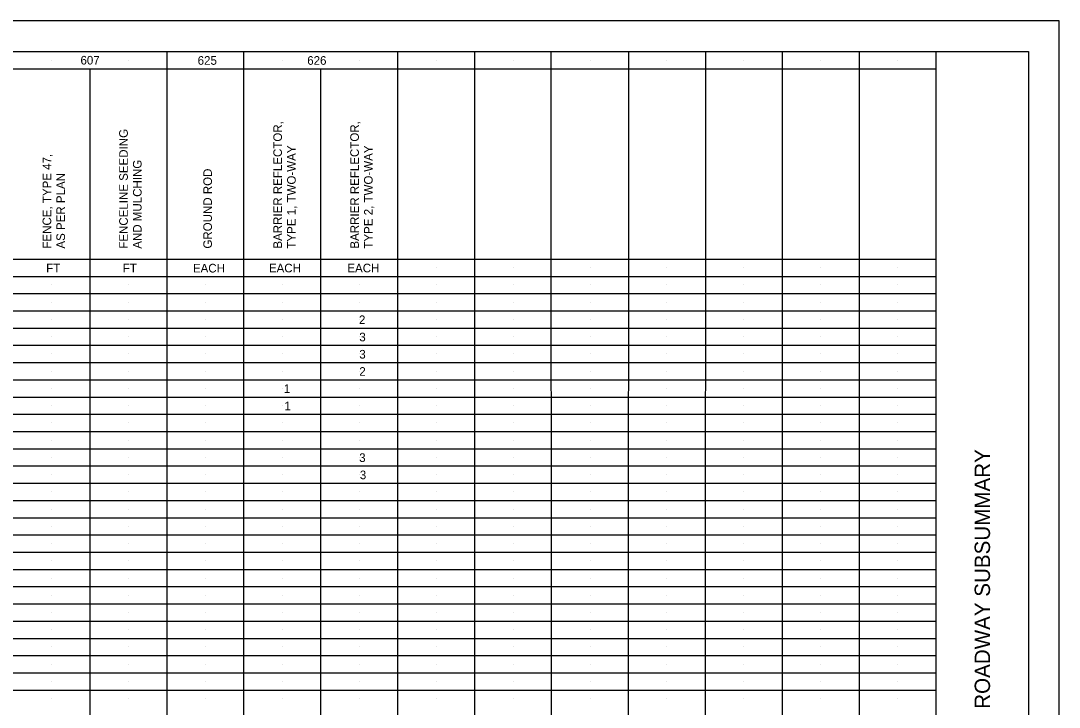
# Model space of a CAD drawing. Extents: x 2073163.9 to 2073197.9, y 634076.5 to 634098.5.
# Drawn here: x 2073181.07 to 2073197.95, y 634087.4 to 634098.55 of the extents above; entities that cross this region are included whole.
import ezdxf

# ---------------------------------------------------------------- set-up
doc = ezdxf.new("R2010")
doc.units = 0
for name, color, linetype in [('SH_Border', 7, 'Continuous'), ('SH_Cut_Line', 7, 'Continuous'), ('SH_Data', 7, 'Continuous'), ('SH_Text', 7, 'Continuous')]:
    doc.layers.add(name, color=color, linetype=linetype)

msp = doc.modelspace()

# ---------------------------------------------------------------- linework, layer by layer
at = {"layer": 'SH_Border'}
msp.add_line((2073195.946, 634077.05), (2073195.946, 634098.05), dxfattribs=at)
msp.add_lwpolyline([(2073165.446, 634098.05), (2073197.446, 634098.05), (2073197.446, 634077.05), (2073165.446, 634077.05)], close=True, dxfattribs=at)
at = {"layer": 'SH_Cut_Line'}
msp.add_lwpolyline([(2073163.946, 634076.55), (2073197.946, 634076.55), (2073197.946, 634098.55), (2073163.946, 634098.55)], close=True, dxfattribs=at)
at = {"layer": 'SH_Data'}
for p, q in [((2073183.446, 634077.05), (2073183.447, 634098.05)), ((2073184.696, 634077.05), (2073184.696, 634098.05)), ((2073187.196, 634077.05), (2073187.196, 634098.05)), ((2073188.446, 634077.05), (2073188.446, 634098.05)), ((2073189.696, 634077.05), (2073189.69, 634098.048)), ((2073190.946, 634077.05), (2073190.95, 634098.05)), ((2073192.196, 634077.05), (2073192.2, 634098.05)), ((2073193.446, 634077.05), (2073193.45, 634098.05)), ((2073194.696, 634077.047), (2073194.7, 634098.047)), ((2073181.571, 634097.91), (2073181.571, 634097.91)), ((2073181.571, 634097.91), (2073181.571, 634097.91)), ((2073182.821, 634097.91), (2073182.821, 634097.91)), ((2073182.821, 634097.91), (2073182.821, 634097.91)), ((2073182.821, 634097.91), (2073182.821, 634097.91)), ((2073184.071, 634097.91), (2073184.071, 634097.91)), ((2073184.071, 634097.91), (2073184.071, 634097.91)), ((2073184.071, 634097.91), (2073184.071, 634097.91)), ((2073184.071, 634097.91), (2073184.071, 634097.91)), ((2073185.321, 634097.91), (2073185.321, 634097.91)), ((2073185.321, 634097.91), (2073185.321, 634097.91)), ((2073185.321, 634097.91), (2073185.321, 634097.91)), ((2073185.321, 634097.91), (2073185.321, 634097.91)), ((2073185.321, 634097.91), (2073185.321, 634097.91)), ((2073186.571, 634097.91), (2073186.571, 634097.91)), ((2073187.821, 634097.91), (2073187.821, 634097.91)), ((2073189.071, 634097.91), (2073189.071, 634097.91)), ((2073190.321, 634097.91), (2073190.321, 634097.91)), ((2073191.571, 634097.91), (2073191.571, 634097.91)), ((2073192.821, 634097.91), (2073192.821, 634097.91)), ((2073194.071, 634097.91), (2073194.071, 634097.91)), ((2073195.321, 634097.91), (2073195.321, 634097.91)), ((2073172.201, 634097.77), (2073195.946, 634097.77)), ((2073182.196, 634077.05), (2073182.196, 634097.77)), ((2073185.946, 634077.05), (2073185.946, 634097.77)), ((2073172.201, 634094.678), (2073195.946, 634094.678)), ((2073181.571, 634094.538), (2073181.571, 634094.538)), ((2073181.571, 634094.538), (2073181.571, 634094.538)), ((2073182.821, 634094.538), (2073182.821, 634094.538)), ((2073182.821, 634094.538), (2073182.821, 634094.538)), ((2073182.821, 634094.538), (2073182.821, 634094.538)), ((2073184.071, 634094.538), (2073184.071, 634094.538)), ((2073184.071, 634094.538), (2073184.071, 634094.538)), ((2073184.071, 634094.538), (2073184.071, 634094.538)), ((2073184.071, 634094.538), (2073184.071, 634094.538)), ((2073185.321, 634094.538), (2073185.321, 634094.538)), ((2073185.321, 634094.538), (2073185.321, 634094.538)), ((2073185.321, 634094.538), (2073185.321, 634094.538)), ((2073185.321, 634094.538), (2073185.321, 634094.538)), ((2073185.321, 634094.538), (2073185.321, 634094.538)), ((2073186.571, 634094.538), (2073186.571, 634094.538)), ((2073187.821, 634094.538), (2073187.821, 634094.538)), ((2073189.071, 634094.538), (2073189.071, 634094.538)), ((2073190.321, 634094.538), (2073190.321, 634094.538)), ((2073191.571, 634094.538), (2073191.571, 634094.538)), ((2073192.821, 634094.538), (2073192.821, 634094.538)), ((2073194.071, 634094.538), (2073194.071, 634094.538)), ((2073195.321, 634094.538), (2073195.321, 634094.538)), ((2073165.446, 634094.398), (2073195.946, 634094.398)), ((2073181.571, 634094.258), (2073181.571, 634094.258)), ((2073182.821, 634094.258), (2073182.821, 634094.258)), ((2073184.071, 634094.258), (2073184.071, 634094.258)), ((2073185.321, 634094.258), (2073185.321, 634094.258)), ((2073186.571, 634094.258), (2073186.571, 634094.258)), ((2073187.821, 634094.258), (2073187.821, 634094.258)), ((2073189.071, 634094.258), (2073189.071, 634094.258)), ((2073190.321, 634094.258), (2073190.321, 634094.258)), ((2073191.571, 634094.258), (2073191.571, 634094.258)), ((2073192.821, 634094.258), (2073192.821, 634094.258)), ((2073194.071, 634094.258), (2073194.071, 634094.258)), ((2073195.321, 634094.258), (2073195.321, 634094.258)), ((2073165.44, 634094.118), (2073195.948, 634094.118)), ((2073181.571, 634093.978), (2073181.571, 634093.978)), ((2073182.821, 634093.978), (2073182.821, 634093.978)), ((2073184.071, 634093.978), (2073184.071, 634093.978)), ((2073185.321, 634093.978), (2073185.321, 634093.978)), ((2073186.571, 634093.978), (2073186.571, 634093.978)), ((2073187.821, 634093.978), (2073187.821, 634093.978)), ((2073189.071, 634093.978), (2073189.071, 634093.978)), ((2073190.321, 634093.978), (2073190.321, 634093.978)), ((2073191.571, 634093.978), (2073191.571, 634093.978)), ((2073192.821, 634093.978), (2073192.821, 634093.978)), ((2073194.071, 634093.978), (2073194.071, 634093.978)), ((2073195.321, 634093.978), (2073195.321, 634093.978)), ((2073165.45, 634093.838), (2073195.947, 634093.838)), ((2073181.571, 634093.698), (2073181.571, 634093.698)), ((2073182.821, 634093.698), (2073182.821, 634093.698)), ((2073184.071, 634093.698), (2073184.071, 634093.698)), ((2073185.321, 634093.698), (2073185.321, 634093.698)), ((2073186.571, 634093.698), (2073186.571, 634093.698)), ((2073187.821, 634093.698), (2073187.821, 634093.698)), ((2073189.071, 634093.698), (2073189.071, 634093.698)), ((2073190.321, 634093.698), (2073190.321, 634093.698)), ((2073191.571, 634093.698), (2073191.571, 634093.698)), ((2073192.821, 634093.698), (2073192.821, 634093.698)), ((2073194.071, 634093.698), (2073194.071, 634093.698)), ((2073195.321, 634093.698), (2073195.321, 634093.698)), ((2073165.45, 634093.558), (2073195.947, 634093.558)), ((2073181.571, 634093.418), (2073181.571, 634093.418)), ((2073182.821, 634093.418), (2073182.821, 634093.418)), ((2073184.071, 634093.418), (2073184.071, 634093.418)), ((2073185.321, 634093.418), (2073185.321, 634093.418)), ((2073186.571, 634093.418), (2073186.571, 634093.418)), ((2073187.821, 634093.418), (2073187.821, 634093.418)), ((2073189.071, 634093.418), (2073189.071, 634093.418)), ((2073190.321, 634093.418), (2073190.321, 634093.418)), ((2073191.571, 634093.418), (2073191.571, 634093.418)), ((2073192.821, 634093.418), (2073192.821, 634093.418)), ((2073194.071, 634093.418), (2073194.071, 634093.418)), ((2073195.321, 634093.418), (2073195.321, 634093.418)), ((2073165.447, 634093.278), (2073195.949, 634093.278)), ((2073181.571, 634093.138), (2073181.571, 634093.138)), ((2073182.821, 634093.138), (2073182.821, 634093.138)), ((2073184.071, 634093.138), (2073184.071, 634093.138)), ((2073185.321, 634093.138), (2073185.321, 634093.138)), ((2073186.571, 634093.138), (2073186.571, 634093.138)), ((2073187.821, 634093.138), (2073187.821, 634093.138)), ((2073189.071, 634093.138), (2073189.071, 634093.138)), ((2073190.321, 634093.138), (2073190.321, 634093.138)), ((2073191.571, 634093.138), (2073191.571, 634093.138)), ((2073192.821, 634093.138), (2073192.821, 634093.138)), ((2073194.071, 634093.138), (2073194.071, 634093.138)), ((2073195.321, 634093.138), (2073195.321, 634093.138)), ((2073165.444, 634092.998), (2073195.947, 634092.998)), ((2073181.571, 634092.858), (2073181.571, 634092.858)), ((2073182.821, 634092.858), (2073182.821, 634092.858)), ((2073184.071, 634092.858), (2073184.071, 634092.858)), ((2073185.321, 634092.858), (2073185.321, 634092.858)), ((2073186.571, 634092.858), (2073186.571, 634092.858)), ((2073187.821, 634092.858), (2073187.821, 634092.858)), ((2073189.071, 634092.858), (2073189.071, 634092.858)), ((2073190.321, 634092.858), (2073190.321, 634092.858)), ((2073191.571, 634092.858), (2073191.571, 634092.858)), ((2073192.821, 634092.858), (2073192.821, 634092.858)), ((2073194.071, 634092.858), (2073194.071, 634092.858)), ((2073195.321, 634092.858), (2073195.321, 634092.858)), ((2073165.454, 634092.718), (2073195.947, 634092.718)), ((2073181.571, 634092.578), (2073181.571, 634092.578)), ((2073182.821, 634092.578), (2073182.821, 634092.578)), ((2073184.071, 634092.578), (2073184.071, 634092.578)), ((2073185.321, 634092.578), (2073185.321, 634092.578)), ((2073186.571, 634092.578), (2073186.571, 634092.578)), ((2073187.821, 634092.578), (2073187.821, 634092.578)), ((2073189.071, 634092.578), (2073189.071, 634092.578)), ((2073190.321, 634092.578), (2073190.321, 634092.578)), ((2073191.571, 634092.578), (2073191.571, 634092.578)), ((2073192.821, 634092.578), (2073192.821, 634092.578)), ((2073194.071, 634092.578), (2073194.071, 634092.578)), ((2073195.321, 634092.578), (2073195.321, 634092.578)), ((2073165.45, 634092.438), (2073195.943, 634092.438)), ((2073181.571, 634092.298), (2073181.571, 634092.298)), ((2073182.821, 634092.298), (2073182.821, 634092.298)), ((2073184.071, 634092.298), (2073184.071, 634092.298)), ((2073185.321, 634092.298), (2073185.321, 634092.298)), ((2073186.571, 634092.298), (2073186.571, 634092.298)), ((2073187.821, 634092.298), (2073187.821, 634092.298)), ((2073189.071, 634092.298), (2073189.071, 634092.298)), ((2073190.321, 634092.298), (2073190.321, 634092.298)), ((2073191.571, 634092.298), (2073191.571, 634092.298)), ((2073192.821, 634092.298), (2073192.821, 634092.298)), ((2073194.071, 634092.298), (2073194.071, 634092.298)), ((2073195.321, 634092.298), (2073195.321, 634092.298)), ((2073165.448, 634092.158), (2073195.943, 634092.158)), ((2073181.571, 634092.018), (2073181.571, 634092.018)), ((2073182.821, 634092.018), (2073182.821, 634092.018)), ((2073184.071, 634092.018), (2073184.071, 634092.018)), ((2073185.321, 634092.018), (2073185.321, 634092.018)), ((2073186.571, 634092.018), (2073186.571, 634092.018)), ((2073187.821, 634092.018), (2073187.821, 634092.018)), ((2073189.071, 634092.018), (2073189.071, 634092.018)), ((2073190.321, 634092.018), (2073190.321, 634092.018)), ((2073191.571, 634092.018), (2073191.571, 634092.018)), ((2073192.821, 634092.018), (2073192.821, 634092.018)), ((2073194.071, 634092.018), (2073194.071, 634092.018)), ((2073195.321, 634092.018), (2073195.321, 634092.018)), ((2073165.448, 634091.878), (2073195.943, 634091.878)), ((2073181.571, 634091.738), (2073181.571, 634091.738)), ((2073182.821, 634091.738), (2073182.821, 634091.738)), ((2073184.071, 634091.738), (2073184.071, 634091.738)), ((2073185.321, 634091.738), (2073185.321, 634091.738)), ((2073186.571, 634091.738), (2073186.571, 634091.738)), ((2073187.821, 634091.738), (2073187.821, 634091.738)), ((2073189.071, 634091.738), (2073189.071, 634091.738)), ((2073190.321, 634091.738), (2073190.321, 634091.738)), ((2073191.571, 634091.738), (2073191.571, 634091.738)), ((2073192.821, 634091.738), (2073192.821, 634091.738)), ((2073194.071, 634091.738), (2073194.071, 634091.738)), ((2073195.321, 634091.738), (2073195.321, 634091.738)), ((2073165.448, 634091.598), (2073195.948, 634091.598)), ((2073181.571, 634091.458), (2073181.571, 634091.458)), ((2073182.821, 634091.458), (2073182.821, 634091.458)), ((2073184.071, 634091.458), (2073184.071, 634091.458)), ((2073185.321, 634091.458), (2073185.321, 634091.458)), ((2073186.571, 634091.458), (2073186.571, 634091.458)), ((2073187.821, 634091.458), (2073187.821, 634091.458)), ((2073189.071, 634091.458), (2073189.071, 634091.458)), ((2073190.321, 634091.458), (2073190.321, 634091.458)), ((2073191.571, 634091.458), (2073191.571, 634091.458)), ((2073192.821, 634091.458), (2073192.821, 634091.458)), ((2073194.071, 634091.458), (2073194.071, 634091.458)), ((2073195.321, 634091.458), (2073195.321, 634091.458)), ((2073165.451, 634091.318), (2073195.939, 634091.318)), ((2073165.451, 634091.318), (2073195.944, 634091.318)), ((2073181.571, 634091.178), (2073181.571, 634091.178)), ((2073182.821, 634091.178), (2073182.821, 634091.178)), ((2073184.071, 634091.178), (2073184.071, 634091.178)), ((2073185.321, 634091.178), (2073185.321, 634091.178)), ((2073186.571, 634091.178), (2073186.571, 634091.178)), ((2073187.821, 634091.178), (2073187.821, 634091.178)), ((2073189.071, 634091.178), (2073189.071, 634091.178)), ((2073190.321, 634091.178), (2073190.321, 634091.178)), ((2073191.571, 634091.178), (2073191.571, 634091.178)), ((2073192.821, 634091.178), (2073192.821, 634091.178)), ((2073194.071, 634091.178), (2073194.071, 634091.178)), ((2073195.321, 634091.178), (2073195.321, 634091.178)), ((2073165.448, 634091.038), (2073195.944, 634091.038)), ((2073181.571, 634090.898), (2073181.571, 634090.898)), ((2073182.821, 634090.898), (2073182.821, 634090.898)), ((2073184.071, 634090.898), (2073184.071, 634090.898)), ((2073185.321, 634090.898), (2073185.321, 634090.898)), ((2073186.571, 634090.898), (2073186.571, 634090.898)), ((2073187.821, 634090.898), (2073187.821, 634090.898)), ((2073189.071, 634090.898), (2073189.071, 634090.898)), ((2073190.321, 634090.898), (2073190.321, 634090.898)), ((2073191.571, 634090.898), (2073191.571, 634090.898)), ((2073192.821, 634090.898), (2073192.821, 634090.898)), ((2073194.071, 634090.898), (2073194.071, 634090.898)), ((2073195.321, 634090.898), (2073195.321, 634090.898)), ((2073165.445, 634090.758), (2073195.942, 634090.758)), ((2073181.571, 634090.618), (2073181.571, 634090.618)), ((2073182.821, 634090.618), (2073182.821, 634090.618)), ((2073184.071, 634090.618), (2073184.071, 634090.618)), ((2073185.321, 634090.618), (2073185.321, 634090.618)), ((2073186.571, 634090.618), (2073186.571, 634090.618)), ((2073187.821, 634090.618), (2073187.821, 634090.618)), ((2073189.071, 634090.618), (2073189.071, 634090.618)), ((2073190.321, 634090.618), (2073190.321, 634090.618)), ((2073191.571, 634090.618), (2073191.571, 634090.618)), ((2073192.821, 634090.618), (2073192.821, 634090.618)), ((2073194.071, 634090.618), (2073194.071, 634090.618)), ((2073195.321, 634090.618), (2073195.321, 634090.618)), ((2073165.442, 634090.478), (2073195.946, 634090.478)), ((2073181.571, 634090.338), (2073181.571, 634090.338)), ((2073182.821, 634090.338), (2073182.821, 634090.338)), ((2073184.071, 634090.338), (2073184.071, 634090.338)), ((2073185.321, 634090.338), (2073185.321, 634090.338)), ((2073186.571, 634090.338), (2073186.571, 634090.338)), ((2073187.821, 634090.338), (2073187.821, 634090.338)), ((2073189.071, 634090.338), (2073189.071, 634090.338)), ((2073190.321, 634090.338), (2073190.321, 634090.338)), ((2073191.571, 634090.338), (2073191.571, 634090.338)), ((2073192.821, 634090.338), (2073192.821, 634090.338)), ((2073194.071, 634090.338), (2073194.071, 634090.338)), ((2073195.321, 634090.338), (2073195.321, 634090.338)), ((2073165.442, 634090.198), (2073195.946, 634090.198)), ((2073181.571, 634090.058), (2073181.571, 634090.058)), ((2073182.821, 634090.058), (2073182.821, 634090.058)), ((2073184.071, 634090.058), (2073184.071, 634090.058)), ((2073185.321, 634090.058), (2073185.321, 634090.058)), ((2073186.571, 634090.058), (2073186.571, 634090.058)), ((2073187.821, 634090.058), (2073187.821, 634090.058)), ((2073189.071, 634090.058), (2073189.071, 634090.058)), ((2073190.321, 634090.058), (2073190.321, 634090.058)), ((2073191.571, 634090.058), (2073191.571, 634090.058)), ((2073192.821, 634090.058), (2073192.821, 634090.058)), ((2073194.071, 634090.058), (2073194.071, 634090.058)), ((2073195.321, 634090.058), (2073195.321, 634090.058)), ((2073165.446, 634089.918), (2073195.946, 634089.918)), ((2073181.571, 634089.778), (2073181.571, 634089.778)), ((2073182.821, 634089.778), (2073182.821, 634089.778)), ((2073184.071, 634089.778), (2073184.071, 634089.778)), ((2073185.321, 634089.778), (2073185.321, 634089.778)), ((2073186.571, 634089.778), (2073186.571, 634089.778)), ((2073187.821, 634089.778), (2073187.821, 634089.778)), ((2073189.071, 634089.778), (2073189.071, 634089.778)), ((2073190.321, 634089.778), (2073190.321, 634089.778)), ((2073191.571, 634089.778), (2073191.571, 634089.778)), ((2073192.821, 634089.778), (2073192.821, 634089.778)), ((2073194.071, 634089.778), (2073194.071, 634089.778)), ((2073195.321, 634089.778), (2073195.321, 634089.778)), ((2073165.446, 634089.638), (2073195.946, 634089.638)), ((2073181.571, 634089.498), (2073181.571, 634089.498)), ((2073182.821, 634089.498), (2073182.821, 634089.498)), ((2073184.071, 634089.498), (2073184.071, 634089.498)), ((2073185.321, 634089.498), (2073185.321, 634089.498)), ((2073186.571, 634089.498), (2073186.571, 634089.498)), ((2073187.821, 634089.498), (2073187.821, 634089.498)), ((2073189.071, 634089.498), (2073189.071, 634089.498)), ((2073190.321, 634089.498), (2073190.321, 634089.498)), ((2073191.571, 634089.498), (2073191.571, 634089.498)), ((2073192.821, 634089.498), (2073192.821, 634089.498)), ((2073194.071, 634089.498), (2073194.071, 634089.498)), ((2073195.321, 634089.498), (2073195.321, 634089.498)), ((2073165.446, 634089.358), (2073195.946, 634089.358)), ((2073181.571, 634089.218), (2073181.571, 634089.218)), ((2073182.821, 634089.218), (2073182.821, 634089.218)), ((2073184.071, 634089.218), (2073184.071, 634089.218)), ((2073185.321, 634089.218), (2073185.321, 634089.218)), ((2073186.571, 634089.218), (2073186.571, 634089.218)), ((2073187.821, 634089.218), (2073187.821, 634089.218)), ((2073189.071, 634089.218), (2073189.071, 634089.218)), ((2073190.321, 634089.218), (2073190.321, 634089.218)), ((2073191.571, 634089.218), (2073191.571, 634089.218)), ((2073192.821, 634089.218), (2073192.821, 634089.218)), ((2073194.071, 634089.218), (2073194.071, 634089.218)), ((2073195.321, 634089.218), (2073195.321, 634089.218)), ((2073165.446, 634089.078), (2073195.946, 634089.078)), ((2073181.571, 634088.938), (2073181.571, 634088.938)), ((2073182.821, 634088.938), (2073182.821, 634088.938)), ((2073184.071, 634088.938), (2073184.071, 634088.938)), ((2073185.321, 634088.938), (2073185.321, 634088.938)), ((2073186.571, 634088.938), (2073186.571, 634088.938)), ((2073187.821, 634088.938), (2073187.821, 634088.938)), ((2073189.071, 634088.938), (2073189.071, 634088.938)), ((2073190.321, 634088.938), (2073190.321, 634088.938)), ((2073191.571, 634088.938), (2073191.571, 634088.938)), ((2073192.821, 634088.938), (2073192.821, 634088.938)), ((2073194.071, 634088.938), (2073194.071, 634088.938)), ((2073195.321, 634088.938), (2073195.321, 634088.938)), ((2073165.446, 634088.798), (2073195.946, 634088.798)), ((2073181.571, 634088.658), (2073181.571, 634088.658)), ((2073182.821, 634088.658), (2073182.821, 634088.658)), ((2073184.071, 634088.658), (2073184.071, 634088.658)), ((2073185.321, 634088.658), (2073185.321, 634088.658)), ((2073186.571, 634088.658), (2073186.571, 634088.658)), ((2073187.821, 634088.658), (2073187.821, 634088.658)), ((2073189.071, 634088.658), (2073189.071, 634088.658)), ((2073190.321, 634088.658), (2073190.321, 634088.658)), ((2073191.571, 634088.658), (2073191.571, 634088.658)), ((2073192.821, 634088.658), (2073192.821, 634088.658)), ((2073194.071, 634088.658), (2073194.071, 634088.658)), ((2073195.321, 634088.658), (2073195.321, 634088.658)), ((2073165.446, 634088.518), (2073195.946, 634088.518)), ((2073165.446, 634088.238), (2073195.946, 634088.238)), ((2073181.571, 634088.378), (2073181.571, 634088.378)), ((2073182.821, 634088.378), (2073182.821, 634088.378)), ((2073184.071, 634088.378), (2073184.071, 634088.378)), ((2073185.321, 634088.378), (2073185.321, 634088.378)), ((2073186.571, 634088.378), (2073186.571, 634088.378)), ((2073187.821, 634088.378), (2073187.821, 634088.378)), ((2073189.071, 634088.378), (2073189.071, 634088.378)), ((2073190.321, 634088.378), (2073190.321, 634088.378)), ((2073191.571, 634088.378), (2073191.571, 634088.378)), ((2073192.821, 634088.378), (2073192.821, 634088.378)), ((2073194.071, 634088.378), (2073194.071, 634088.378)), ((2073195.321, 634088.378), (2073195.321, 634088.378)), ((2073181.571, 634088.098), (2073181.571, 634088.098)), ((2073182.821, 634088.098), (2073182.821, 634088.098)), ((2073184.071, 634088.098), (2073184.071, 634088.098)), ((2073185.321, 634088.098), (2073185.321, 634088.098)), ((2073186.571, 634088.098), (2073186.571, 634088.098)), ((2073187.821, 634088.098), (2073187.821, 634088.098)), ((2073189.071, 634088.098), (2073189.071, 634088.098)), ((2073190.321, 634088.098), (2073190.321, 634088.098)), ((2073191.571, 634088.098), (2073191.571, 634088.098)), ((2073192.821, 634088.098), (2073192.821, 634088.098)), ((2073194.071, 634088.098), (2073194.071, 634088.098)), ((2073195.321, 634088.098), (2073195.321, 634088.098)), ((2073165.446, 634087.958), (2073195.946, 634087.958)), ((2073181.571, 634087.818), (2073181.571, 634087.818)), ((2073182.821, 634087.818), (2073182.821, 634087.818)), ((2073184.071, 634087.818), (2073184.071, 634087.818)), ((2073185.321, 634087.818), (2073185.321, 634087.818)), ((2073186.571, 634087.818), (2073186.571, 634087.818)), ((2073187.821, 634087.818), (2073187.821, 634087.818)), ((2073189.071, 634087.818), (2073189.071, 634087.818)), ((2073190.321, 634087.818), (2073190.321, 634087.818)), ((2073191.571, 634087.818), (2073191.571, 634087.818)), ((2073192.821, 634087.818), (2073192.821, 634087.818)), ((2073194.071, 634087.818), (2073194.071, 634087.818)), ((2073195.321, 634087.818), (2073195.321, 634087.818)), ((2073165.446, 634087.678), (2073195.946, 634087.678)), ((2073181.571, 634087.538), (2073181.571, 634087.538)), ((2073182.821, 634087.538), (2073182.821, 634087.538)), ((2073184.071, 634087.538), (2073184.071, 634087.538)), ((2073185.321, 634087.538), (2073185.321, 634087.538)), ((2073186.571, 634087.538), (2073186.571, 634087.538)), ((2073187.821, 634087.538), (2073187.821, 634087.538)), ((2073189.071, 634087.538), (2073189.071, 634087.538)), ((2073190.321, 634087.538), (2073190.321, 634087.538)), ((2073191.571, 634087.538), (2073191.571, 634087.538)), ((2073192.821, 634087.538), (2073192.821, 634087.538)), ((2073194.071, 634087.538), (2073194.071, 634087.538)), ((2073195.321, 634087.538), (2073195.321, 634087.538))]:
    msp.add_line(p, q, dxfattribs=at)

# ---------------------------------------------------------------- texts
msp.add_text('ROADWAY SUBSUMMARY', height=0.25, rotation=90, dxfattribs=at).set_placement((2073196.821, 634087.374))
at = {"layer": 'SH_Text'}
for s, rotation, p in [('607', 0.0001, (2073182.04, 634097.839)), ('625', 0.0001, (2073183.944, 634097.835)), ('626', 0.0001, (2073185.725, 634097.835)), ('BARRIER REFLECTOR, ', 90.0001, (2073185.314, 634094.849)), ('BARRIER REFLECTOR, ', 90.0001, (2073186.564, 634094.849)), ('FENCELINE SEEDING', 90.0001, (2073182.809, 634094.847)), ('TYPE 1, TWO-WAY', 90.0001, (2073185.538, 634094.849)), ('TYPE 2, TWO-WAY', 90.0001, (2073186.788, 634094.849)), ('FENCE, TYPE 47, ', 90.0001, (2073181.564, 634094.849)), ('AND MULCHING', 90.0001, (2073183.033, 634094.847)), ('AS PER PLAN', 90.0001, (2073181.788, 634094.849)), ('GROUND ROD', 90.0001, (2073184.176, 634094.849)), ('FT', 0.0001, (2073181.482, 634094.463)), ('FT', 0.0001, (2073182.727, 634094.463)), ('EACH', 0.0001, (2073183.867, 634094.461)), ('EACH', 0.0001, (2073185.102, 634094.463)), ('EACH', 0.0001, (2073186.377, 634094.463)), ('2', 0.0001, (2073186.565, 634093.623)), ('3', 0.0001, (2073186.571, 634093.343)), ('3', 0.0001, (2073186.571, 634093.063)), ('2', 0.0001, (2073186.571, 634092.783)), ('1', 0.0001, (2073185.343, 634092.503)), ('1', 0.0001, (2073185.353, 634092.223)), ('3', 0.0001, (2073186.569, 634091.383)), ('3', 0.0001, (2073186.579, 634091.103))]:
    msp.add_text(s, height=0.14, rotation=rotation, dxfattribs=at).set_placement(p)

doc.saveas('drawing.dxf')
